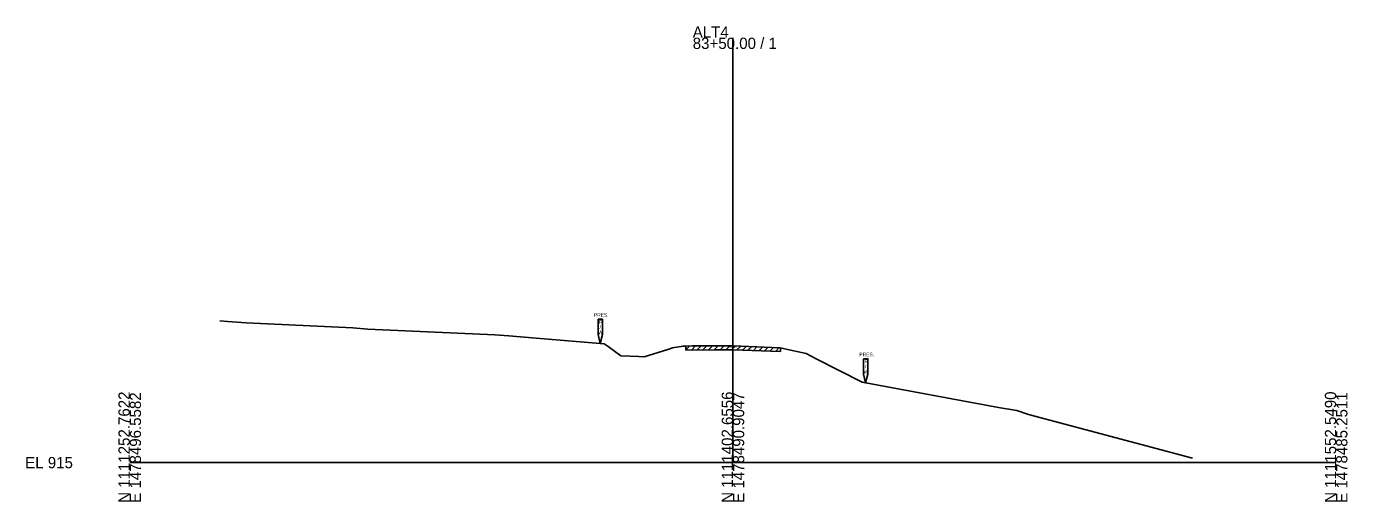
# Model space of a CAD drawing. Extents: x -26 to 1303, y -10 to 19562.
# Drawn here: x -25.7 to 302.8, y -9.7 to 108.5 of the extents above; entities that cross this region are included whole.
import ezdxf

# ---------------------------------------------------------------- set-up
doc = ezdxf.new("R2010")
doc.units = 0
for name, color, linetype in [('RD_GPK_XS_Cell', 7, 'Continuous'), ('RD_XS_ExGround', 7, 'Continuous'), ('RD_XS_ExPaveRet', 7, 'Continuous'), ('RD_XS_ExRW', 7, 'Continuous'), ('RD_XS_TX_Elev_EX', 7, 'Continuous')]:
    doc.layers.add(name, color=color, linetype=linetype)

msp = doc.modelspace()

# ---------------------------------------------------------------- linework, layer by layer
at = {"layer": 'RD_GPK_XS_Cell'}
for p, q in [((150, 0), (150, 105.72)), ((0, 0), (150, 0)), ((150, 0), (300, 0))]:
    msp.add_line(p, q, dxfattribs=at)
at = {"layer": 'RD_XS_ExGround'}
msp.add_lwpolyline([(22.44, 35.24), (24.33, 35.11), (28.93, 34.78), (55.51, 33.53), (59.21, 33.24), (90.82, 31.76), (94.28, 31.52), (101.08, 31), (117.95, 29.56), (118.94, 28.93), (122.16, 26.61), (126.56, 26.39), (127.93, 26.3), (133.77, 28.12), (134.97, 28.57), (137.62, 28.95), (138.13, 29.01), (139.85, 29.02), (150.05, 29.07), (159.63, 28.65), (161.73, 28.57), (162.84, 28.31), (168.22, 27.12), (170.67, 25.83), (182.12, 19.98), (216.05, 13.74), (220.61, 12.94), (223.52, 11.96), (264.3, 1.11)], dxfattribs=at)
at = {"layer": 'RD_XS_ExPaveRet'}
for p, q in [((138.29, 28.06), (139.25, 29.02)), ((138.29, 29.01), (138.29, 28.01)), ((139.67, 28.02), (140.67, 29.02)), ((141.09, 28.03), (142.09, 29.03)), ((142.51, 28.04), (143.51, 29.04)), ((143.94, 28.05), (144.94, 29.05)), ((145.36, 28.06), (146.36, 29.06)), ((146.78, 28.06), (147.78, 29.06)), ((148.2, 28.07), (149.2, 29.07)), ((149.62, 28.08), (150.6, 29.06)), ((151, 28.05), (151.96, 29)), ((152.37, 27.99), (153.33, 28.95)), ((153.73, 27.94), (154.69, 28.9)), ((155.09, 27.89), (156.05, 28.85)), ((156.45, 27.84), (157.41, 28.8)), ((157.82, 27.79), (158.78, 28.75)), ((159.18, 27.74), (160.14, 28.7)), ((160.54, 27.68), (161.5, 28.64)), ((161.8, 28.63), (161.8, 27.63))]:
    msp.add_line(p, q, dxfattribs=at)
msp.add_lwpolyline([(138.29, 28.02), (145.49, 28.06), (150.09, 28.08), (159.4, 27.73), (161.8, 27.64)], dxfattribs=at)
at = {"layer": 'RD_XS_ExRW'}
for points in [[(116.45, 35.67), (117.55, 35.67), (117.55, 31.84), (117, 29.65), (116.45, 31.84)], [(182.45, 25.84), (183.55, 25.84), (183.55, 22.01), (183, 19.83), (182.45, 22.01)]]:
    msp.add_lwpolyline(points, close=True, dxfattribs=at)

# ---------------------------------------------------------------- texts
at = {"layer": 'RD_GPK_XS_Cell'}
for s, p in [('ALT4', (140, 105.72)), ('83+50.00 / 1', (140, 102.92)), ('EL 915', (-26, -1.4))]:
    msp.add_text(s, height=2.8, dxfattribs=at).set_placement(p)
for s, p in [('N 1111252.7622', (0, -10)), ('E 1478496.5582', (2.8, -10)), ('N 1111402.6556', (150, -10)), ('E 1478490.9047', (152.8, -10)), ('N 1111552.5490', (300, -10)), ('E 1478485.2511', (302.8, -10))]:
    msp.add_text(s, height=2.8, rotation=90, dxfattribs=at).set_placement(p)
at = {"layer": 'RD_XS_ExRW'}
for s, p in [('PRES.', (115.45, 36.29)), ('R', (116.71, 34.57)), ('/', (116.83, 33.26)), ('W', (116.53, 31.95)), ('PRES.', (181.45, 26.47)), ('W', (182.53, 22.13)), ('R', (182.71, 24.75)), ('/', (182.83, 23.44))]:
    msp.add_text(s, height=0.875, dxfattribs=at).set_placement(p)
at = {"layer": 'RD_XS_TX_Elev_EX'}
msp.add_text('944.07', height=0.5, dxfattribs=at).set_placement((148.98, 28.57))

doc.saveas('drawing.dxf')
